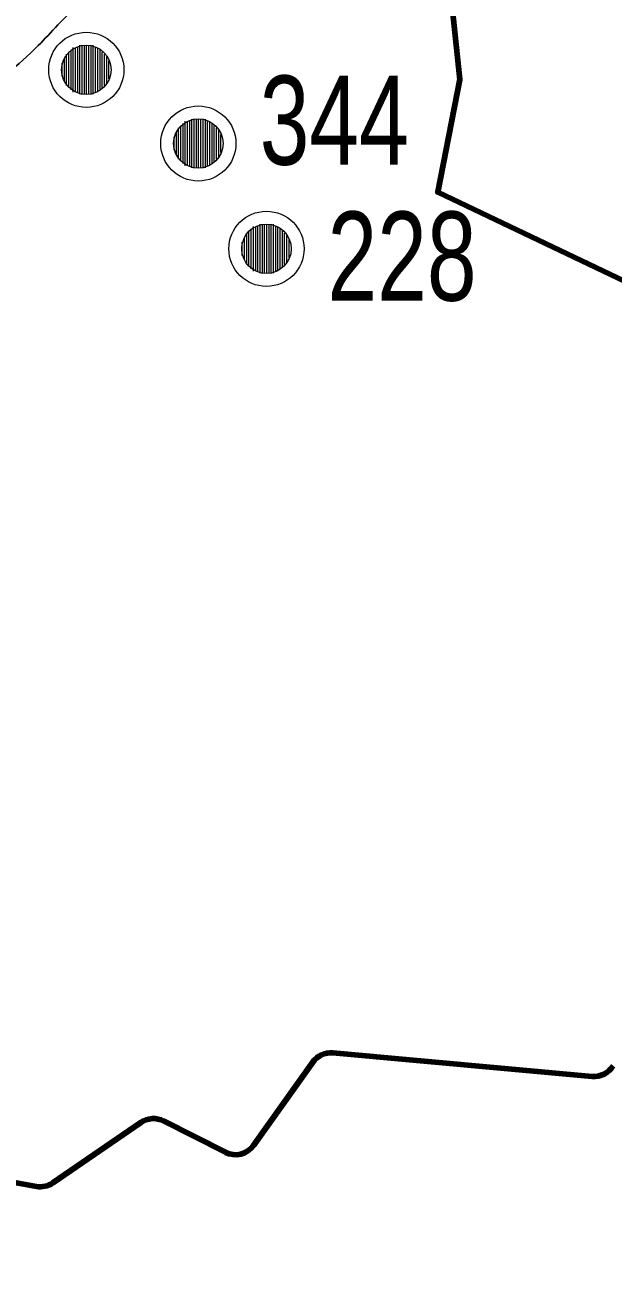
# Model space of a CAD drawing. Extents: x 553962 to 842807, y 8883888 to 9032388.
# Drawn here: x 715683 to 718324, y 8951050 to 8956639 of the extents above; entities that cross this region are included whole.
import ezdxf

# ---------------------------------------------------------------- set-up
doc = ezdxf.new("R2010")
doc.units = 0
doc.header["$LTSCALE"] = 160
for name, color, linetype, lineweight in [('21', 7, 'Continuous', 25), ('27', 7, 'Continuous', 90), ('32', 7, 'Continuous', 13), ('33', 7, 'Continuous', 13), ('7', 7, 'Continuous', 90)]:
    doc.layers.add(name, color=color, linetype=linetype, lineweight=lineweight)

msp = doc.modelspace()

# ---------------------------------------------------------------- linework, layer by layer
at = {"layer": '21'}
msp.add_spline([(716474.8, 8957749), (716354.5, 8957498.3), (716264.3, 8957257.6), (716204.2, 8957027), (716103.9, 8956866.5), (715923.5, 8956726.1), (715743.1, 8956545.6), (715462.4, 8956294.9), (715171.8, 8956004.1), (715115.4, 8955955.8)], degree=3, dxfattribs=at)
at = {"layer": '27'}
msp.add_lwpolyline([(717295.3, 8959630.3), (717636.9, 8956393.6), (717537.2, 8955887), (718376.1, 8955487), (718808.6, 8955185.8), (719472.1, 8954177.6), (719984.6, 8952814.2), (721077.3, 8952390.4), (721486.8, 8951456.6), (721666.8, 8950799.8), (721718.4, 8950547.1), (727920.4, 8947850.3), (733274.5, 8948007.9), (737635.8, 8948628.8)], dxfattribs=at)
at = {"layer": '32'}
for p, q in [((715929, 8956547), (715929, 8956327)), ((715939, 8956547), (715939, 8956327)), ((715949, 8956547), (715949, 8956327)), ((715959, 8956547), (715959, 8956327)), ((715969, 8956547), (715969, 8956327)), ((715979, 8956547), (715979, 8956327)), ((715989, 8956547), (715989, 8956327)), ((715859, 8956487), (715859, 8956387)), ((715869, 8956507), (715869, 8956367)), ((715879, 8956517), (715879, 8956357)), ((715889, 8956527), (715889, 8956347)), ((715899, 8956537), (715899, 8956337)), ((715909, 8956537), (715909, 8956337)), ((715919, 8956537), (715919, 8956337)), ((715999, 8956537), (715999, 8956337)), ((716009, 8956537), (716009, 8956337)), ((716019, 8956527), (716019, 8956347)), ((716029, 8956517), (716029, 8956357)), ((716039, 8956507), (716039, 8956367)), ((716049, 8956497), (716049, 8956377)), ((715849, 8956467), (715849, 8956407)), ((716059, 8956477), (716059, 8956397)), ((716402, 8956206), (716402, 8956006)), ((716412, 8956206), (716412, 8956006)), ((716422, 8956206), (716422, 8956006)), ((716432, 8956216), (716432, 8955996)), ((716442, 8956216), (716442, 8955996)), ((716452, 8956216), (716452, 8955996)), ((716462, 8956216), (716462, 8955996)), ((716472, 8956216), (716472, 8955996)), ((716482, 8956216), (716482, 8955996)), ((716492, 8956216), (716492, 8955996)), ((716502, 8956206), (716502, 8956006)), ((716512, 8956206), (716512, 8956006)), ((716362, 8956156), (716362, 8956056)), ((716372, 8956176), (716372, 8956036)), ((716382, 8956186), (716382, 8956026)), ((716392, 8956196), (716392, 8956016)), ((716522, 8956196), (716522, 8956016)), ((716532, 8956186), (716532, 8956026)), ((716542, 8956176), (716542, 8956036)), ((716552, 8956166), (716552, 8956046)), ((716352, 8956136), (716352, 8956076)), ((716562, 8956146), (716562, 8956066))]:
    msp.add_line(p, q, dxfattribs=at)
for centre, radius in [((715959, 8956437), 168.7), ((715959, 8956437), 111), ((716462, 8956106), 168.7), ((716462, 8956106), 111)]:
    msp.add_circle(centre, radius, dxfattribs=at)
at = {"layer": '33'}
for p, q in [((716678, 8955703), (716678, 8955563)), ((716688, 8955713), (716688, 8955553)), ((716698, 8955723), (716698, 8955543)), ((716708, 8955733), (716708, 8955533)), ((716718, 8955733), (716718, 8955533)), ((716728, 8955733), (716728, 8955533)), ((716738, 8955743), (716738, 8955523)), ((716748, 8955743), (716748, 8955523)), ((716758, 8955743), (716758, 8955523)), ((716768, 8955743), (716768, 8955523)), ((716778, 8955743), (716778, 8955523)), ((716788, 8955743), (716788, 8955523)), ((716798, 8955743), (716798, 8955523)), ((716808, 8955733), (716808, 8955533)), ((716818, 8955733), (716818, 8955533)), ((716828, 8955723), (716828, 8955543)), ((716838, 8955713), (716838, 8955553)), ((716848, 8955703), (716848, 8955563)), ((716658, 8955663), (716658, 8955603)), ((716668, 8955683), (716668, 8955583)), ((716858, 8955693), (716858, 8955573)), ((716868, 8955673), (716868, 8955593))]:
    msp.add_line(p, q, dxfattribs=at)
for radius in [168.7, 111]:
    msp.add_circle((716768, 8955633), radius, dxfattribs=at)
at = {"layer": '7'}
for p, q in [((717066.3, 8952021.2), (718230.2, 8951915.7)), ((716710.3, 8951605.7), (716975.8, 8951979.6)), ((715809.4, 8951437.3), (716204.3, 8951708.5)), ((716306.2, 8951715.3), (716583.5, 8951574.5)), ((715483.8, 8951466.8), (715734.9, 8951421.3))]:
    msp.add_line(p, q, dxfattribs=at)
for centre, start, end in [((717057.3, 8951921.6), 84.8207, 144.6185), ((718239.2, 8952015.3), 264.8207, 328.4726), ((716260.9, 8951626.1), 63.0743, 124.4822), ((716628.7, 8951663.6), 243.0743, 324.6185), ((715752.7, 8951519.7), 259.7299, 304.4822)]:
    msp.add_arc(centre, 100, start, end, dxfattribs=at)

# ---------------------------------------------------------------- texts
at = {"layer": '32', "width": 0.75}
msp.add_text('344', height=400, dxfattribs=at).set_placement((716737.7, 8956010.8))
at = {"layer": '33', "width": 0.75}
msp.add_text('228', height=400, dxfattribs=at).set_placement((717042.2, 8955400.1))

doc.saveas('drawing.dxf')
